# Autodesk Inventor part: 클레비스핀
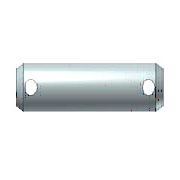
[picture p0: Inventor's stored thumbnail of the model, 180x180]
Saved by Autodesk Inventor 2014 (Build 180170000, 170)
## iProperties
IsCustomPart: 1
Created: 2012-02
Part Number: 클레비스핀
Material: 강철
Description: 머리가 없는 클레비스 핀 B
Document SubType Name: Modeling
Standard: ISO 2340
Designer: mduedu
Standard Revision: Second edition 1986-11-01
Standards Organization: ISO
Language: ko-KR
Size Designation: B - 8 x 45
Categories: <MemberInstance><Categories><Category DisplayName="조임쇠" InternalName="e4da775c-781d-43d5-af7c-5136215cf5a6" Mnemonic="FSTN"><Category DisplayName="핀" InternalNa
Density: 7.85 g/cm^3
Appearance: 강철
Author: mduedu
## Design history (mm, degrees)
sketch "스케치1"
  geometry: L1 (-4.5, 0)-(-4.5, 4); L2 (-4.5, 4)-(40.5, 4); L3 (40.5, 4)-(40.5, 0); L4 (-4.5, 0)-(40.5, 0); L5 (0, -1.46)-(0, 3.16) reference; L6 (-6.4, 0)-(18.8, 0) reference; C1 r 1 at (-1, 0); C2 r 1 at (37, 0)
  constraints: 8 end point, 2 centre point, 2 perpendicular, 2 point on line, 1 collinear, 1 parallel, 1 tangent, 1 vertical
  dimensions: "d0" = 8 diameter of L2 L4 (= NND); "d1" = 45 distance of L1.end L2.end (= NLG); "d2" = 3.5 distance from line of L1 C1.centre (= DIST1); "d3" = 3.5 distance from line of L3 C2.centre (= DIST2); "d4" = 2 diameter of C1 (= BOR1); "d5" = 2 diameter of C2 (= BOR2)
revolve "본체" stored, may be unused: angle "d7" = 90 deg
extrude "구멍1" cut sketch "스케치1" taper "d6" = 0 deg; stored distance "d8" = 10
extrude "구멍2" cut sketch "스케치1" taper "d13" = 0 deg; stored distance "d14" = 10
workaxis "Work Axis1"
workaxis "Work Axis2"
workplane "Work Plane1"
node "작업 평면5"
node "작업 평면8"
body "Solid1"
chamfer "모따기2" distance "d9" = 2 (= PHH2); stored, may be unused: angle "d10" = 30 deg (= FAWI2), second distance "d40" = 2 (= PHH2)
chamfer "모따기1" distance "d11" = 2 (= PHH1); stored, may be unused: angle "d12" = 30 deg (= FAWI1), second distance "d41" = 2 (= PHH1)
other parameters: "NLG" = 45 [user parameter; used in 1 equation term], "NND" = 8 [user parameter; used in 1 equation term], "PHH1" = 2 [user parameter; used in 3 equation terms], "PHH2" = 2 (= PHH1) [user parameter; used in 2 equation terms], "FAWI1" = 30 deg [user parameter; used in 1 equation term], "FAWI2" = 30 deg [user parameter; used in 1 equation term], "DIST1" = 3.5 [user parameter; used in 4 equation terms], "DIST2" = 3.5 (= DIST1) [user parameter; used in 1 equation term], "BOR1" = 2 [user parameter; used in 4 equation terms], "BOR2" = 2 (= BOR1) [user parameter; used in 1 equation term], "d15" = 0, "d42" = 0, "d43" = 0, "d44" = -4.5 (= -0.5 x BOR1 - DIST1), "d45" = -4.5 (= -0.5 x BOR1 - DIST1), "d47" = 0, "d48" = 0, "d49" = 0, "d50" = 0, "d51" = 0, "d52" = 0
